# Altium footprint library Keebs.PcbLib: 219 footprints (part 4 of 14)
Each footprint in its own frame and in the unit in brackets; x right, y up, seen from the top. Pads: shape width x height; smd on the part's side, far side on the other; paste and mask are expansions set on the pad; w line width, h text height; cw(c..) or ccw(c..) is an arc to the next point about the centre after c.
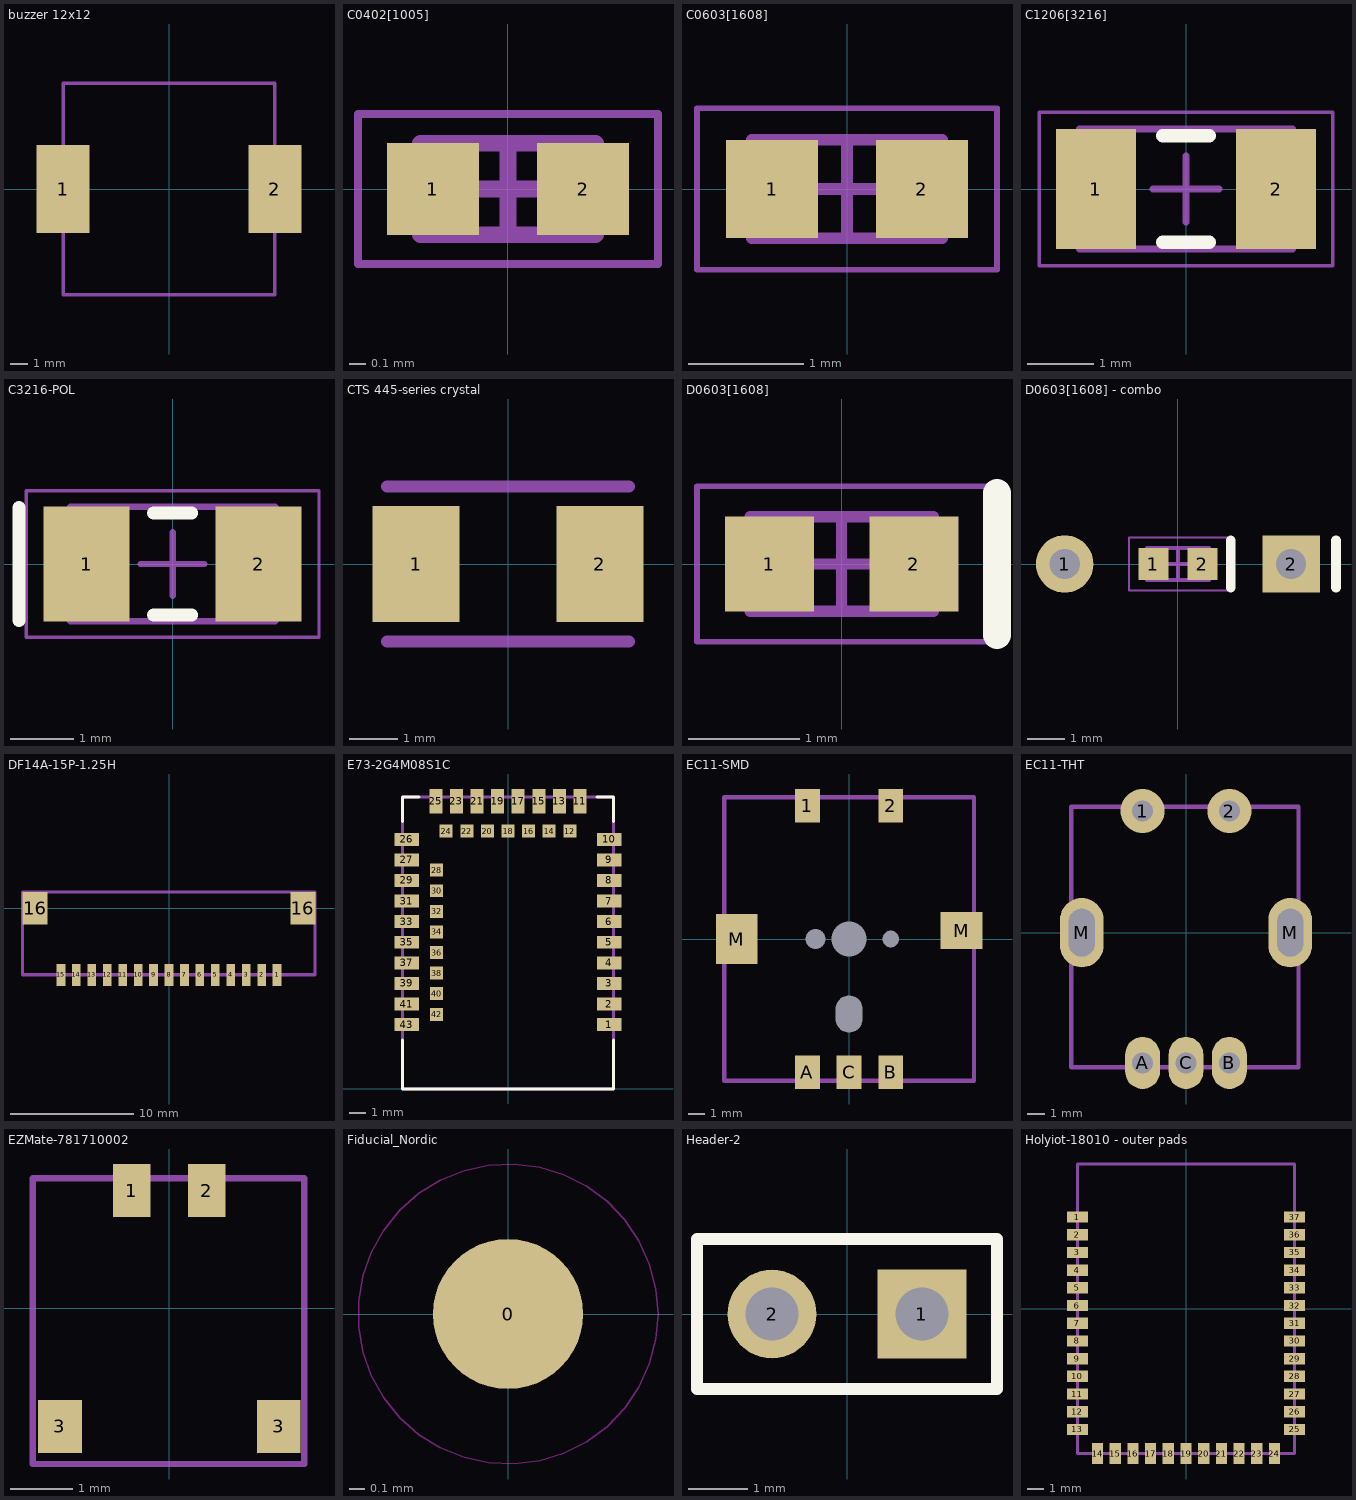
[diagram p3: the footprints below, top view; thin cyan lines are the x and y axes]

## buzzer 12x12 [mm] "Buzzer"
pads (2):
  rect 3x5 smd: 1(-6,0) 2(6,0)
Mechanical 13:
  lines w0.2: -6,-6 6,-6 6,6 -6,6 -6,-6
  text ".Designator" at -2.007,-1.041 h0.5
3D body "CUI_DEVICES_CMT-1203-SMT-TR.step": height 3.05, standoff 0, extent -6,-6 6,6

## C0402[1005] [mm] "Chip Resistor, 2-Leads, Body 1,00x0,50mm, IPC Medium Density"
height 0.5
pads (2):
  rect 0.55x0.55 smd: 1(-0.45,0) 2(0.45,0)
Mechanical 13:
  lines w0.1: -0.525,-0.275 -0.525,0.275 0.525,0.275 0.525,-0.275 -0.525,-0.275
  text ".Designator" at -0.425,-0.1 h0.2
Mechanical 15:
  lines w0.05: -0.9,-0.45 -0.9,0.45 0.9,0.45 0.9,-0.45 -0.9,-0.45
  lines w0.1: -0.275,0 0.275,0 ; 0,-0.275 0,0.275
3D body: height 0.5, standoff 0, extent -0.325,-0.275 0.325,0.275

## C0603[1608] [mm] "Chip Resistor, 2-Leads, Body 1,57x0,80mm, IPC Medium Density"
height 0.5
pads (2):
  rect 0.8x0.85 smd: 1(-0.65,0) 2(0.65,0)
Mechanical 13:
  lines w0.1: -0.825,-0.425 0.825,-0.425 0.825,0.425 -0.825,0.425 -0.825,-0.425
  text ".Designator" at -1.05,-0.275 h0.35
Mechanical 15:
  lines w0.05: -1.3,-0.7 1.3,-0.7 1.3,0.7 -1.3,0.7 -1.3,-0.7
  lines w0.1: -0.425,0 0.425,0 ; 0,-0.425 0,0.425
3D body: height 0.5, standoff 0, extent -0.525,-0.425 0.525,0.425
3D body: height 0.5, standoff 0, extent 0.525,-0.425 0.825,0.425
3D body: height 0.5, standoff 0, extent -0.825,-0.425 -0.525,0.425

## C1206[3216] [mm]
height 1.2
pads (2):
  rect 1.2x1.8 smd: 1(-1.35,0) 2(1.35,0)
Top Overlay:
  lines w0.2: -0.35,-0.8 0.35,-0.8 ; -0.35,0.8 0.35,0.8
Mechanical 13:
  lines w0.1: -1.6,-0.9 1.6,-0.9 1.6,0.9 -1.6,0.9 -1.6,-0.9
  text ".Designator" at -1.245,-0.152 h0.5
Mechanical 15:
  lines w0.05: -2.2,-1.15 2.2,-1.15 2.2,1.15 -2.2,1.15 -2.2,-1.15
  lines w0.1: -0.5,0 0.5,0 ; 0,-0.5 0,0.5
3D body: height 1.2, standoff 0, extent 1.1,-0.9 1.6,0.9
3D body: height 1.2, standoff 0, extent -1.6,-0.9 -1.1,0.9
3D body: height 1.2, standoff 0, extent -1.1,-0.9 1.1,0.9

## C3216-POL [mm] "Chip Capacitor, 2-Leads, Body 3.20x1.60mm, IPC Medium Density"
height 1.8
pads (2):
  rect 1.35x1.8 smd: 1(-1.35,0) 2(1.35,0)
Top Overlay:
  lines w0.2: -2.413,-0.889 -2.413,0.889 ; -0.3,-0.8 0.3,-0.8 ; -0.3,0.8 0.3,0.8
Mechanical 13:
  lines w0.1: -1.61,-0.9 1.61,-0.9 1.61,0.9 -1.61,0.9 -1.61,-0.9
  text ".Designator" at -1.909,-0.145 h0.5
Mechanical 15:
  lines w0.05: -2.3,-1.15 2.3,-1.15 2.3,1.15 -2.3,1.15 -2.3,-1.15
  lines w0.1: -0.5,0 0.5,0 ; 0,-0.5 0,0.5
3D body "Tant Cap SMD size A _ 3216-18.stp": height 1.64, standoff 0.01, extent -1.73,-0.8 1.73,0.8

## CTS 445-series crystal [mm]
pads (2):
  rect 1.8x2.4 smd: 1(-1.9,0) 2(1.9,0)
Mechanical 13:
  lines w0.254: -2.5,-1.6 2.5,-1.6 ; -2.5,1.6 2.5,1.6
  text ".Designator" at -1.372,-0.152 h0.5
3D body "ABM3.STEP": height 1.3, standoff 0, extent -2.5,-1.6 2.5,1.6

## D0603[1608] [mm] "Chip Resistor, 2-Leads, Body 1,57x0,80mm, IPC Medium Density"
height 0.5
pads (2):
  rect 0.8x0.85 smd: 1(-0.65,0) 2(0.65,0)
Top Overlay:
  lines w0.254: 1.397,-0.635 1.397,0.635
Mechanical 13:
  lines w0.1: -0.825,-0.425 0.825,-0.425 0.825,0.425 -0.825,0.425 -0.825,-0.425
  text ".Designator" at -0.675,-0.175 h0.35
Mechanical 15:
  lines w0.05: -1.3,-0.7 1.3,-0.7 1.3,0.7 -1.3,0.7 -1.3,-0.7
  lines w0.1: -0.425,0 0.425,0 ; 0,-0.425 0,0.425
3D body "CD0603-B0xR.STP": height 0.59, standoff -0.01, extent -0.8,-0.45 0.805,0.45

## D0603[1608] - combo [mm] "Chip Resistor, 2-Leads, Body 1,57x0,80mm, IPC Medium Density"
height 0.5
pads (4):
  round 1.524 hole 0.8: 1(-3,0)
  rect 0.8x0.85 smd: 1(-0.65,0) 2(0.65,0)
  rect 1.524x1.524 hole 0.8: 2(3,0)
Top Overlay:
  lines w0.254: 1.397,-0.635 1.397,0.635 ; 4.191,-0.635 4.191,0.635
Mechanical 13:
  lines w0.1: -0.825,-0.425 -0.825,0.425 0.825,0.425 0.825,-0.425 -0.825,-0.425
  text ".Designator" at -0.675,-0.175 h0.35
Mechanical 15:
  lines w0.05: -1.3,-0.7 -1.3,0.7 1.3,0.7 1.3,-0.7 -1.3,-0.7
  lines w0.1: -0.425,0 0.425,0 ; 0,-0.425 0,0.425
3D body "CD0603-B0xR.STP": height 0.59, standoff -0.01, extent -0.8,-0.45 0.805,0.45

## DF14A-15P-1.25H [mm]
pads (17):
  rect 0.7x1.8 smd: 1(8.75,-5.4) 2(7.5,-5.4) 3(6.25,-5.4) 4(5,-5.4) 5(3.75,-5.4) 6(2.5,-5.4) 7(1.25,-5.4) 8(0,-5.4) 9(-1.25,-5.4) 10(-2.5,-5.4) 11(-3.75,-5.4) 12(-5,-5.4) 13(-6.25,-5.4) 14(-7.5,-5.4) 15(-8.75,-5.4)
  rect 2x2.6 smd: 16(-10.85,0) 16(10.85,0)
Mechanical 13:
  lines w0.254: -11.875,-5.385 -11.875,1.315 11.825,1.315 11.825,-5.385 -11.875,-5.385
  text ".Designator" at -3.226,-1.702 h0.5

## E73-2G4M08S1C [mm]
pads (43):
  rect 1.5x0.8 smd: 1(6.25,3.97) 2(6.25,5.24) 3(6.25,6.51) 4(6.25,7.78) 5(6.25,9.05) 6(6.25,10.32) 7(6.25,11.59) 8(6.25,12.86) 9(6.25,14.13) 10(6.25,15.4) 26(-6.25,15.4) 27(-6.25,14.13) 29(-6.25,12.86) 31(-6.25,11.59) 33(-6.25,10.32) 35(-6.25,9.05) 37(-6.25,7.78) 39(-6.25,6.51) 41(-6.25,5.24) 43(-6.25,3.97)
  rect 0.8x1.5 smd: 11(4.44,17.75) 13(3.17,17.75) 15(1.9,17.75) 17(0.63,17.75) 19(-0.64,17.75) 21(-1.91,17.75) 23(-3.18,17.75) 25(-4.45,17.75)
  rect 0.8x0.8 smd: 12(3.81,15.9) 14(2.54,15.9) 16(1.27,15.9) 18(0,15.9) 20(-1.27,15.9) 22(-2.54,15.9) 24(-3.81,15.9) 28(-4.4,13.495) 30(-4.4,12.225) 32(-4.4,10.955) 34(-4.4,9.685) 36(-4.4,8.415) 38(-4.4,7.145) 40(-4.4,5.875) 42(-4.4,4.605)
Top Overlay:
  lines w0.2: -6.5,3 -6.5,0 6.5,0 6.5,3 ; -6.5,16.5 -6.5,18 -5.5,18 ; 5.5,18 6.5,18 6.5,16.5
Mechanical 13:
  lines w0.2: -6.5,0 -6.5,18 6.5,18 6.5,0 -6.5,0
  text ".Designator" at -1.93,9.296 h0.5
3D body "E73-2G4M08S1C.step": height 3, standoff 0.18, extent -6.604,0.017 6.396,18.017

## EC11-SMD [mm]
pads (11):
  rect 1.5x2 smd: 1(-2.5,8) 2(2.5,8) A(-2.5,-8) B(2.5,-8) C(0,-8)
  rect 2.5x3 smd: M(-6.75,0)
  rect 2.5x2.2 smd: M(6.75,0.508)
  round 0 hole 1.2 unplated: ""(-2,0)
  round 0 hole 1.6 slot 2.2 at 90 deg unplated: ""(0,-4.5)
  round 0 hole 2.1 unplated: ""(0,0)
  round 0 hole 1 unplated: ""(2.5,0)
Mechanical 13:
  lines w0.254: -7.493,-8.509 -7.493,8.509 7.493,8.509 7.493,-8.509 -7.493,-8.509
  text ".Designator" at -2.286,2.032 h0.5
3D body "EC11-SMD-15F-blue.step": height 19.5, standoff -0.8, extent -7.5,-8.5 7.5,8.5

## EC11-THT [mm]
pads (7):
  round 2.54 hole 1.2: 1(-2.5,7) 2(2.5,7)
  oval 2x3 hole 1.2: A(-2.5,-7.5) B(2.5,-7.5) C(0,-7.5)
  oval 2.5x4 hole 1.5 slot 2.75 at 90 deg: M(-6,0) M(6,0)
Mechanical 13:
  lines w0.254: -6.604,-7.747 6.477,-7.747 6.477,7.239 -6.604,7.239 -6.604,-7.747
  text ".Designator" at -2.286,2.032 h0.5
3D body "EC11E-15SW.STEP": height 25.9, standoff -2.1, extent -6.549,-7.724 6.549,7.225

## EZMate-781710002 [mm]
pads (4):
  rect 0.6x0.85 smd: 1(-0.6,1.887) 2(0.6,1.887)
  rect 0.7x0.85 smd: 3(-1.75,-1.887) 3(1.75,-1.887)
Mechanical 13:
  lines w0.1: -2.184,-2.489 -2.184,2.083 2.159,2.083 2.159,-2.489 -2.184,-2.489
  text ".Designator" at -1.676,-0.813 h0.7
3D body "781710002.stp": height 1.45, standoff 0, extent -2.113,-2.447 2.087,2.083

## Fiducial_Nordic [mm]
pads (1):
  round 1 smd paste+0 mask+0.5: 0(0,0)
Top Layer keep-out:
  circle w0.01: c0,0 r1

## Header-2 [mm]
pads (2):
  rect 1.5x1.5 hole 0.9: 1(1.27,0)
  round 1.5 hole 0.9: 2(-1.27,0)
Top Overlay:
  lines w0.2: -2.54,-1.27 2.54,-1.27 2.54,1.27 -2.54,1.27 -2.54,-1.27

## Holyiot-18010 - outer pads [mm] "Holyiot long range Nordic nRF52840 chipset BLE module Ceramic Antenna Bluetooth low Energy for Bluetooth mesh"
pads (37):
  rect 1.3x0.7 smd: 1(-6.75,5.7) 2(-6.75,4.6) 3(-6.75,3.5) 4(-6.75,2.4) 5(-6.75,1.3) 6(-6.75,0.2) 7(-6.75,-0.9) 8(-6.75,-2) 9(-6.75,-3.1) 10(-6.75,-4.2) 11(-6.75,-5.3) 12(-6.75,-6.4) 13(-6.75,-7.5) 25(6.75,-7.5) 26(6.75,-6.4) 27(6.75,-5.3) 28(6.75,-4.2) 29(6.75,-3.1) 30(6.75,-2) 31(6.75,-0.9) 32(6.75,0.2) 33(6.75,1.3) 34(6.75,2.4) 35(6.75,3.5) 36(6.75,4.6) 37(6.75,5.7)
  rect 0.7x1.3 smd: 14(-5.5,-9) 15(-4.4,-9) 16(-3.3,-9) 17(-2.2,-9) 18(-1.1,-9) 19(0,-9) 20(1.1,-9) 21(2.2,-9) 22(3.3,-9) 23(4.4,-9) 24(5.5,-9)
Mechanical 13:
  lines w0.2: -6.75,-9 6.75,-9 6.75,9 -6.75,9 -6.75,-9
  text ".Designator" at -1.306,2.061 h0.35
Mechanical 15:
  lines w0.2: -6.75,7 -6.75,-9 6.75,-9 6.75,7
3D body "Holyiot_18010_v2.step": height 1.92, standoff 0, extent -6.75,-9 6.75,9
